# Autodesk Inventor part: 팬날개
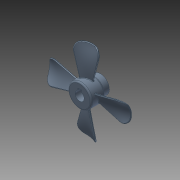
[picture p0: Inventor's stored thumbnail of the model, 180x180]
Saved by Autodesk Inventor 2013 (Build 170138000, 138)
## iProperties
Company: 한국ATC센터
Created: 2016-06
Part Number: 팬날개
Document SubType Name: Modeling
Designer: mdu
Density: 1.06 g/cm^3
Material: ABS 플라스틱
Mass: 29.2304 g
Surface Area: 148.222 cm^2
Volume: 27.5759 cm^3
Author: mdu
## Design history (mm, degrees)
sketch "스케치1"
  geometry: L1 (-15, 0)-(15, 0); L2 (-15, 0)-(-15, 17); L3 (-15, 17)-(5, 17); L4 (5, 17)-(5, 13); L5 (5, 13)-(15, 13); L6 (15, 13)-(15, 0); 2 further points
  constraints: 12 end point, 3 parallel, 2 perpendicular, 1 coincident, 1 horizontal, 1 midpoint
  dimensions: "d0" = 30 distance of L1.start L1.end; "d8" = 34 diameter of L3 L1; "d10" = 26 diameter of L5 L1; "d32" = 20 distance of L2.end L3.end
revolve "회전1" sketch "스케치1" stored, may be unused: angle "d11" = 90 deg
node "작업 평면2"
sketch "스케치7"
  geometry: L1 (-15, 17)-(5, 17) reference; L2 (-15, -17)-(5, -17) reference; L3 (-5, 17)-(-5, -17); A1 r 35 centre (-36.399, -13.457) between (-2, -7) and (-8, 7); 1 further point
  constraints: 2 end point, 2 midpoint, 2 point on circle, 1 centre point
  dimensions: "d36" = 35 radius of A1; "d37" = 10 distance from line of A1.start L2; "d38" = 10 distance from line of A1.end L1; "d45" = 3 distance from line of A1.end L3; "d46" = 3 distance from line of A1.start L3
sketch "3D 스케치1"
  geometry: L1 through (0, 0) direction (1, 0) reference; L2 through (0, 0) direction (1, 0) reference; 13 other entities
  constraints: 2 collinear
  node "투영 원본 위치 스케치7"
sketch "스케치8"
  geometry: L1 (-15, 17)-(5, 17) reference; L2 (-15, -17)-(5, -17) reference; L3 (-5, 17)-(-5, -17); A1 r 30 centre (-28.74, -3.591) between (-3, -19) and (-9, 19); 1 further point
  constraints: 2 end point, 2 midpoint, 2 point on circle, 1 centre point
  dimensions: "d43" = 30 radius of A1; "d47" = 4 distance from line of A1.end L3; "d48" = 2 distance from line of A1.start L3; "d58" = 2 distance from line of A1.end L1; "d59" = 2 distance from line of A1.start L2
sketch "3D 스케치2"
sketch "3D 스케치3"
feature "경계 패치1" sketch "3D 스케치2", "3D 스케치3" dims "d50" = 0
feature "연장1" dims "d55" = 2
feature "두껍게 하기1" dims "d51" = 2, "d52" = 2
sketch "스케치9"
  geometry: C1 r 59 at (0, 0); 1 further point
  constraints: 1 centre point, 1 coincident
  dimensions: "d60" = 118 diameter of C1
extrude "돌출2" sketch "스케치9" distance "d62" = 200; taper "d63" = 0 deg
fillet "모깎기6" dims "d64" = 10
fillet "모깎기7" dims "d66" = 0.8
fillet "모깎기8" dims "d67" = 0.8
sketch "스케치2"
  geometry: L1 (-2.5, 6)-(-2.5, 8.8); L2 (-2.5, 8.8)-(2.5, 8.8); L3 (2.5, 8.8)-(2.5, 6); A1 r 6.5 centre (0, 0) between (-2.5, 6) and (2.5, 6); 1 further point
  constraints: 6 end point, 2 parallel, 2 point on circle, 1 centre point, 1 coincident, 1 horizontal, 1 vertical
  dimensions: "d12" = 13 diameter of A1; "d13" = 5 distance of L1.end L2.end; "d14" = 15.3 dimension on A1 L2 (computed from d12)
extrude "돌출1" cut sketch "스케치2" stored distance "d15" = 10; taper "d16" = 0 deg
chamfer "모따기1" distance "d17" = 1; stored, may be unused: second distance "d18" = 2, angle "d19" = 45 deg
node "작업 평면1"
sketch "스케치3"
  geometry: L1 (5, -13)-(5, 13) reference; 3 further points
  constraints: 1 horizontal alignment, 1 midpoint
  dimensions: "d20" = 5 distance from line of L1 point (0, 0)
hole "구멍1" sketch "스케치3" at (0, 0) diameter "d21" = 3.242; stored, may be unused: countersink angle "d25" = 90 deg, drill point angle "d27" = 118 deg; dims "d22" = 6, "d23" = 4, "d24" = 2, "d26" = 8
fillet "모깎기9" dims "d77" = 2
fillet "모깎기10" dims "d78" = 2
fillet "모깎기11" dims "d79" = 2
node "솔리드1"
pattern_circular "원형 패턴1" dims "d69" = 360 deg
pattern_circular "원형 패턴2" dims angle "d72" = 360 deg
pattern_circular "원형 패턴3" dims angle "d75" = 360 deg
node "투영 원본 위치 스케치8"
node "곡면1"
node "곡면2"
node "곡면3"
node "곡면4"
feature "경계 패치2"
feature "경계 패치3"
feature "경계 패치4"
